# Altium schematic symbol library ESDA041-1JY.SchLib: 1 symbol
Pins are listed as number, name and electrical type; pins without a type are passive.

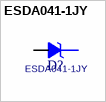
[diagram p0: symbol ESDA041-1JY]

## ESDA041-1JY
designator D?
footprint ST_SOD323
pins: 1 K, 2 A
